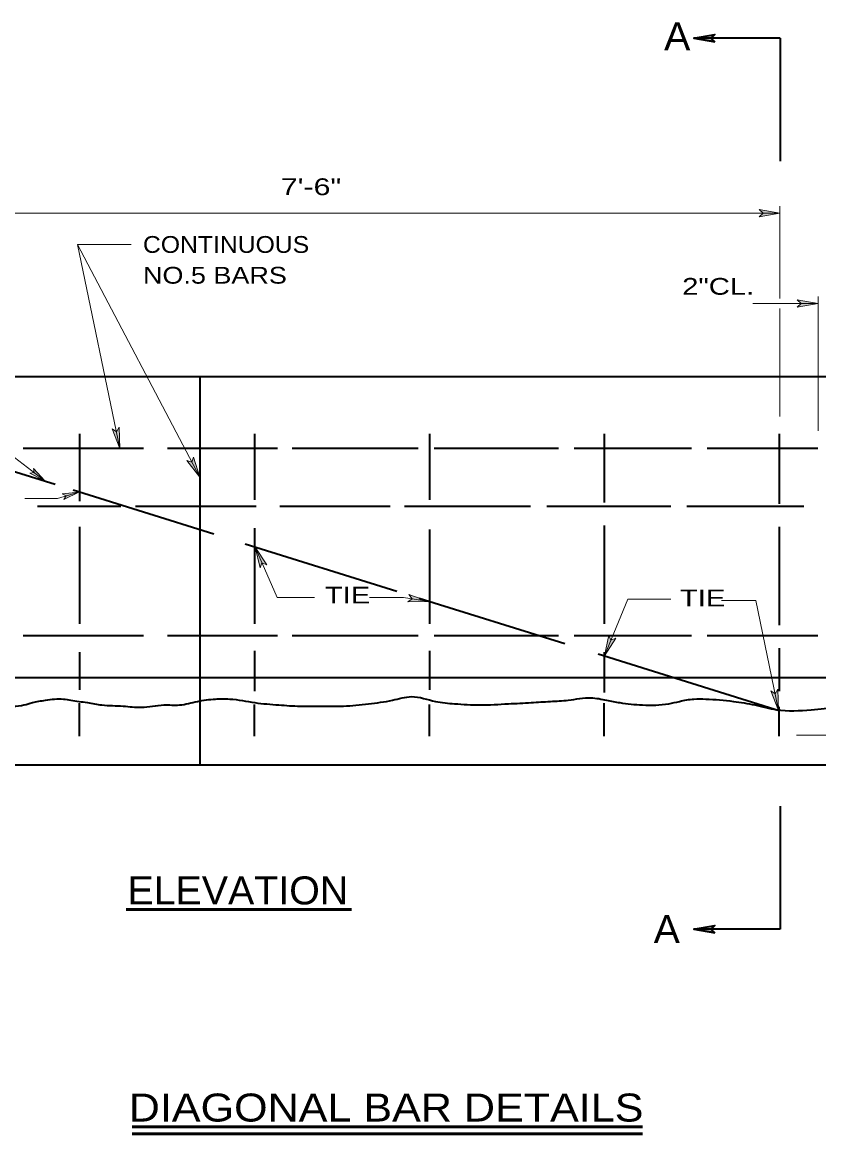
# Model space of a CAD drawing. Extents: x -111.57 to -104.56, y -202.94 to -194.51.
# Drawn here: x -109.851 to -107.008, y -198.476 to -194.506 of the extents above; entities that cross this region are included whole.
import ezdxf
from ezdxf.enums import TextEntityAlignment as Align

# ---------------------------------------------------------------- set-up
doc = ezdxf.new("R2010")
doc.units = 0
doc.header["$LTSCALE"] = 0.024
for name, color, linetype, lineweight in [('1', 7, 'Continuous', 35), ('10', 7, 'Continuous', 13), ('12', 7, 'Continuous', 53)]:
    doc.layers.add(name, color=color, linetype=linetype, lineweight=lineweight)

msp = doc.modelspace()

# ---------------------------------------------------------------- hatches: boundary and pattern name
at = {"layer": '10'}
for points in [[(-107.37917, -194.5755), (-107.45367, -194.56233), (-107.37917, -194.54917), (-107.39317, -194.56233)], [(-107.221, -195.175), (-107.1465, -195.18817), (-107.221, -195.20133), (-107.207, -195.18817)], [(-107.08517, -195.49717), (-107.01067, -195.51033), (-107.08517, -195.5235), (-107.07117, -195.51033)], [(-109.505, -195.95233), (-109.50267, -196.028), (-109.53067, -195.95767), (-109.515, -195.96883)], [(-109.24033, -196.059), (-109.21717, -196.131), (-109.2635, -196.07117), (-109.24533, -196.0775)], [(-109.81117, -196.09917), (-109.77033, -196.14383), (-109.824, -196.11583), (-109.80867, -196.11433)], [(-109.70867, -196.19067), (-109.6485, -196.184), (-109.70283, -196.21083), (-109.69483, -196.1975)], [(-109.002, -196.4545), (-109.02017, -196.38117), (-108.978, -196.444), (-108.99567, -196.43633)], [(-108.471, -196.55017), (-108.3995, -196.57483), (-108.475, -196.57617), (-108.45917, -196.56533)], [(-107.7325, -196.70533), (-107.773, -196.76933), (-107.75683, -196.69533), (-107.75, -196.71333)], [(-107.15367, -196.88833), (-107.15133, -196.96383), (-107.17933, -196.89367), (-107.16367, -196.90467)], [(-107.37917, -197.758), (-107.45367, -197.745), (-107.37917, -197.73183), (-107.39317, -197.745)]]:
    msp.add_hatch(color=256, dxfattribs=at).paths.add_polyline_path(points)

# ---------------------------------------------------------------- linework, layer by layer
at = {"layer": '1'}
for p, q in [((-106.9415, -195.77267), (-111.493, -195.77267)), ((-109.21717, -195.77267), (-109.21717, -197.15983)), ((-110.29317, -195.98067), (-109.73333, -196.156)), ((-109.6465, -195.976), (-109.6465, -196.2165)), ((-109.02217, -195.976), (-109.02217, -196.21183)), ((-108.398, -195.976), (-108.398, -196.21183)), ((-107.77383, -195.976), (-107.77383, -196.22133)), ((-107.14967, -195.976), (-107.14967, -196.22617)), ((-109.41783, -196.028), (-109.848, -196.028)), ((-108.9395, -196.028), (-109.33233, -196.028)), ((-108.43833, -196.028), (-108.88733, -196.028)), ((-107.93733, -196.028), (-108.38017, -196.028)), ((-107.46217, -196.028), (-107.88067, -196.028)), ((-107.01083, -196.028), (-107.40667, -196.028)), ((-109.669, -196.17617), (-109.16733, -196.33317)), ((-109.499, -196.235), (-109.7965, -196.235)), ((-109.0165, -196.235), (-109.44683, -196.235)), ((-108.53833, -196.235), (-108.93117, -196.235)), ((-108.03717, -196.235), (-108.48617, -196.235)), ((-107.536, -196.235), (-107.979, -196.235)), ((-107.061, -196.235), (-107.47933, -196.235)), ((-109.6465, -196.308), (-109.6465, -196.65417)), ((-109.02217, -196.31267), (-109.02217, -196.65417)), ((-108.398, -196.3175), (-108.398, -196.65417)), ((-107.77383, -196.303), (-107.77383, -196.65417)), ((-107.14967, -196.308), (-107.14967, -196.659)), ((-109.05483, -196.36833), (-108.51383, -196.53767)), ((-108.43467, -196.56233), (-107.91467, -196.72517)), ((-109.41783, -196.69733), (-109.848, -196.69733)), ((-108.9395, -196.69733), (-109.33233, -196.69733)), ((-108.43833, -196.69733), (-108.88733, -196.69733)), ((-107.93733, -196.69733), (-108.38017, -196.69733)), ((-107.46217, -196.69733), (-107.88067, -196.69733)), ((-107.01083, -196.69733), (-107.40667, -196.69733)), ((-109.6465, -196.75517), (-109.6465, -196.89)), ((-109.02217, -196.7505), (-109.02217, -196.89467)), ((-108.398, -196.7505), (-108.398, -196.89)), ((-107.77383, -196.75517), (-107.77383, -196.8995)), ((-107.14967, -196.74083), (-107.14967, -196.89467)), ((-107.14583, -196.96583), (-107.795, -196.76267)), ((-106.9415, -196.84767), (-111.493, -196.84767)), ((-109.6465, -197.05567), (-109.6465, -196.938)), ((-109.02217, -197.05567), (-109.02217, -196.94283)), ((-108.398, -197.05567), (-108.398, -196.94283)), ((-107.77383, -197.05567), (-107.77383, -196.938)), ((-107.14967, -197.05567), (-107.14967, -196.9505))]:
    msp.add_line(p, q, dxfattribs=at)
msp.add_lwpolyline([(-106.9415, -195.77267), (-106.9415, -197.15983), (-111.493, -197.15983)], dxfattribs=at)
msp.add_spline([(-110.89483, -196.95167), (-110.80983, -196.9485), (-110.77133, -196.93583), (-110.73283, -196.9315), (-110.70733, -196.94417), (-110.68167, -196.95267), (-110.66033, -196.95267), (-110.639, -196.9485), (-110.61333, -196.94417), (-110.5835, -196.94), (-110.54933, -196.94), (-110.528, -196.94), (-110.50667, -196.9485), (-110.45967, -196.9485), (-110.42117, -196.9485), (-110.36567, -196.93583), (-110.323, -196.9315), (-110.29317, -196.92717), (-110.28033, -196.94), (-110.2505, -196.95267), (-110.19483, -196.95267), (-110.15217, -196.9485), (-110.08817, -196.93583), (-110.02417, -196.92717), (-109.99417, -196.9315), (-109.96433, -196.94), (-109.88317, -196.9485), (-109.84483, -196.94417), (-109.81483, -196.93583), (-109.768, -196.92717), (-109.704, -196.923), (-109.67817, -196.92717), (-109.6185, -196.93583), (-109.56717, -196.94417), (-109.49033, -196.9485), (-109.42633, -196.95267), (-109.34517, -196.94417), (-109.28967, -196.94417), (-109.22567, -196.9315), (-109.1615, -196.923), (-109.11033, -196.923), (-109.02067, -196.93583), (-108.93533, -196.94417), (-108.8585, -196.9485), (-108.773, -196.9485), (-108.70467, -196.9485), (-108.615, -196.94), (-108.52967, -196.92717), (-108.46133, -196.9145), (-108.376, -196.9315), (-108.30767, -196.94), (-108.21783, -196.94417), (-108.1155, -196.94), (-108.03433, -196.93583), (-107.966, -196.9315), (-107.902, -196.92717), (-107.82083, -196.91867), (-107.76533, -196.92717), (-107.71833, -196.93583), (-107.63717, -196.94417), (-107.54333, -196.94), (-107.50483, -196.9315), (-107.45367, -196.923), (-107.411, -196.923), (-107.31267, -196.9315), (-107.23583, -196.94417), (-107.159, -196.96117), (-107.03517, -196.96117), (-106.9415, -196.95167)], degree=3, dxfattribs=at)
at = {"layer": '10', "lineweight": 35}
for p, q in [((-107.45367, -194.56233), (-107.37917, -194.54917)), ((-107.14567, -194.56233), (-107.45367, -194.56233)), ((-107.45367, -194.56233), (-107.37917, -194.5755)), ((-107.14567, -194.56233), (-107.14567, -195.00183)), ((-107.14567, -197.3055), (-107.14567, -197.745)), ((-107.45367, -197.745), (-107.37917, -197.73183)), ((-107.14567, -197.745), (-107.45367, -197.745)), ((-107.45367, -197.745), (-107.37917, -197.758))]:
    msp.add_line(p, q, dxfattribs=at)
at = {"layer": '10'}
for p, q in [((-107.1465, -195.16317), (-107.1465, -195.49283)), ((-110.272, -195.18817), (-107.1465, -195.18817)), ((-107.1465, -195.18817), (-107.221, -195.175)), ((-107.1465, -195.18817), (-107.221, -195.20133)), ((-109.21717, -196.131), (-109.654, -195.2995)), ((-107.01067, -195.9655), (-107.01067, -195.48533)), ((-107.01067, -195.51033), (-107.24367, -195.51033)), ((-107.01067, -195.51033), (-107.08517, -195.49717)), ((-107.01067, -195.51033), (-107.08517, -195.5235)), ((-107.1465, -195.9135), (-107.1465, -195.52783)), ((-109.50267, -196.028), (-109.53067, -195.95767)), ((-109.50267, -196.028), (-109.505, -195.95233)), ((-109.21717, -196.131), (-109.2635, -196.07117)), ((-109.21717, -196.131), (-109.24033, -196.059)), ((-109.77033, -196.14383), (-109.824, -196.11583)), ((-109.77033, -196.14383), (-109.81117, -196.09917)), ((-109.7255, -196.2065), (-109.6485, -196.184)), ((-109.6485, -196.184), (-109.70867, -196.19067)), ((-109.6485, -196.184), (-109.70283, -196.21083)), ((-109.84233, -196.2065), (-109.7255, -196.2065)), ((-108.94083, -196.5605), (-109.02017, -196.38117)), ((-109.02017, -196.38117), (-109.002, -196.4545)), ((-109.02017, -196.38117), (-108.978, -196.444)), ((-108.3995, -196.57483), (-108.471, -196.55017)), ((-108.80817, -196.5605), (-108.94083, -196.5605)), ((-108.612, -196.5605), (-108.48983, -196.5605)), ((-108.48983, -196.5605), (-108.3995, -196.57483)), ((-108.3995, -196.57483), (-108.475, -196.57617)), ((-107.35517, -196.571), (-107.23317, -196.571)), ((-107.23317, -196.571), (-107.15133, -196.96383)), ((-107.773, -196.76933), (-107.75683, -196.69533)), ((-107.773, -196.76933), (-107.7325, -196.70533)), ((-107.15133, -196.96383), (-107.17933, -196.89367)), ((-107.15133, -196.96383), (-107.15367, -196.88833)), ((-107.08717, -197.05167), (-105.78133, -197.05167))]:
    msp.add_line(p, q, dxfattribs=at)
at = {"layer": '10', "lineweight": 35}
for points in [[(-107.37917, -194.5755), (-107.45367, -194.56233), (-107.37917, -194.54917), (-107.39317, -194.56233)], [(-107.37917, -197.758), (-107.45367, -197.745), (-107.37917, -197.73183), (-107.39317, -197.745)]]:
    msp.add_lwpolyline(points, close=True, dxfattribs=at)
for points in [[(-107.37917, -194.5755), (-107.39317, -194.56233), (-107.37917, -194.54917)], [(-107.37917, -197.758), (-107.39317, -197.745), (-107.37917, -197.73183)]]:
    msp.add_lwpolyline(points, dxfattribs=at)
at = {"layer": '10'}
for points in [[(-107.221, -195.175), (-107.207, -195.18817), (-107.221, -195.20133)], [(-109.50267, -196.028), (-109.654, -195.2995), (-109.46183, -195.2995)], [(-111.129, -195.525), (-110.5755, -195.525), (-109.77033, -196.14383)], [(-107.08517, -195.49717), (-107.07117, -195.51033), (-107.08517, -195.5235)], [(-109.505, -195.95233), (-109.515, -195.96883), (-109.53067, -195.95767)], [(-109.24033, -196.059), (-109.24533, -196.0775), (-109.2635, -196.07117)], [(-109.81117, -196.09917), (-109.80867, -196.11433), (-109.824, -196.11583)], [(-109.70867, -196.19067), (-109.69483, -196.1975), (-109.70283, -196.21083)], [(-109.002, -196.4545), (-108.99567, -196.43633), (-108.978, -196.444)], [(-108.471, -196.55017), (-108.45917, -196.56533), (-108.475, -196.57617)], [(-107.5355, -196.56583), (-107.68967, -196.56583), (-107.773, -196.76933)], [(-107.7325, -196.70533), (-107.75, -196.71333), (-107.75683, -196.69533)], [(-107.15367, -196.88833), (-107.16367, -196.90467), (-107.17933, -196.89367)]]:
    msp.add_lwpolyline(points, dxfattribs=at)
for points in [[(-107.221, -195.175), (-107.1465, -195.18817), (-107.221, -195.20133), (-107.207, -195.18817)], [(-107.08517, -195.49717), (-107.01067, -195.51033), (-107.08517, -195.5235), (-107.07117, -195.51033)], [(-109.505, -195.95233), (-109.50267, -196.028), (-109.53067, -195.95767), (-109.515, -195.96883)], [(-109.24033, -196.059), (-109.21717, -196.131), (-109.2635, -196.07117), (-109.24533, -196.0775)], [(-109.81117, -196.09917), (-109.77033, -196.14383), (-109.824, -196.11583), (-109.80867, -196.11433)], [(-109.70867, -196.19067), (-109.6485, -196.184), (-109.70283, -196.21083), (-109.69483, -196.1975)], [(-109.002, -196.4545), (-109.02017, -196.38117), (-108.978, -196.444), (-108.99567, -196.43633)], [(-108.471, -196.55017), (-108.3995, -196.57483), (-108.475, -196.57617), (-108.45917, -196.56533)], [(-107.7325, -196.70533), (-107.773, -196.76933), (-107.75683, -196.69533), (-107.75, -196.71333)], [(-107.15367, -196.88833), (-107.15133, -196.96383), (-107.17933, -196.89367), (-107.16367, -196.90467)]]:
    msp.add_lwpolyline(points, close=True, dxfattribs=at)
at = {"layer": '12'}
for p, q in [((-109.48, -197.67517), (-108.6755, -197.67517)), ((-109.45883, -198.45083), (-107.637, -198.45083)), ((-109.45883, -198.47583), (-107.637, -198.47583))]:
    msp.add_line(p, q, dxfattribs=at)

# ---------------------------------------------------------------- texts
at = {"layer": '12', "width": 1.05}
for p in [(-107.46642, -194.60575), (-107.50367, -197.795)]:
    msp.add_text('A', height=0.1, dxfattribs=at).set_placement(p, align=Align.RIGHT)
at = {"layer": '12'}
for s, width, p in [('7\'-6"', 1.35, (-108.92817, -195.12333)), ('CONTINUOUS', 1.1, (-109.42017, -195.3295)), ('NO.5 BARS', 1.2, (-109.42017, -195.4395)), ('2"CL.', 1.3, (-107.49558, -195.47917)), ('TIE', 1.3, (-108.77092, -196.58167)), ('TIE', 1.3, (-107.50358, -196.59217))]:
    msp.add_text(s, height=0.06, dxfattribs=dict(at, width=width)).set_placement(p)
for s, width, p in [('ELEVATION', 1.05, (-109.08154, -197.65658)), ('DIAGONAL BAR DETAILS', 1.15, (-108.55225, -198.43217))]:
    msp.add_text(s, height=0.1, dxfattribs=dict(at, width=width)).set_placement(p, align=Align.CENTER)

doc.saveas('drawing.dxf')
